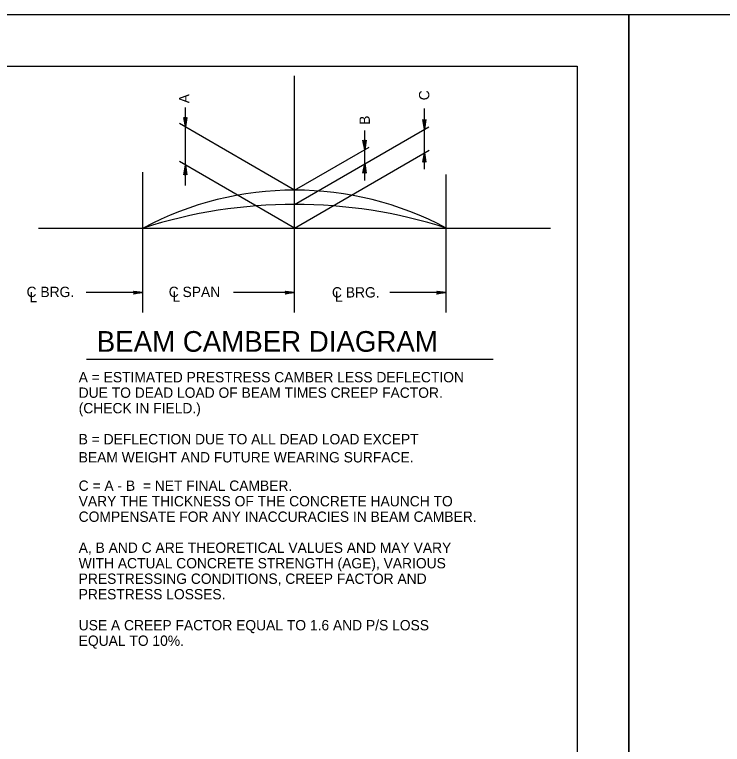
# Model space of a CAD drawing. Extents: x 637933 to 640019, y 298854 to 300042.
# Drawn here: x 638646.7 to 638852.1, y 299830.3 to 300042.1 of the extents above; entities that cross this region are included whole.
import ezdxf

# ---------------------------------------------------------------- set-up
doc = ezdxf.new("R2010")
doc.units = 0
doc.layers.add('1', color=7, linetype='Continuous')
doc.layers.add('PLT-BNDY', color=7, linetype='Continuous')

msp = doc.modelspace()

# ---------------------------------------------------------------- linework, layer by layer
at = {"layer": '1'}
for p, q in [((638023.93, 300027.12), (638809.94, 300027.12)), ((638809.94, 300027.12), (638809.94, 299463.12)), ((638727.89, 299955.63), (638727.89, 300024.38)), ((638696.26, 300009.5), (638696.26, 300015.13)), ((638765.64, 300008.88), (638765.64, 300014.88)), ((638727.89, 299991.13), (638694.51, 300010.5)), ((638696.26, 299998.5), (638696.26, 300009.5)), ((638727.89, 299987), (638766.89, 300009.5)), ((638748.26, 300002.88), (638748.26, 300008.5)), ((638765.64, 300002), (638765.64, 300008.75)), ((638727.89, 299991.13), (638749.51, 300003.63)), ((638727.89, 299980.13), (638767.01, 300002.75)), ((638748.26, 299998.88), (638748.26, 300002.88)), ((638765.64, 299997.25), (638765.64, 300002)), ((638727.89, 299980.13), (638694.51, 299999.5)), ((638696.26, 299992.5), (638696.26, 299998.38)), ((638748.26, 299994), (638748.26, 299998.88)), ((638683.89, 299955.63), (638683.89, 299996.38)), ((638771.89, 299955.63), (638771.89, 299995.75)), ((638727.89, 299991.13), (638727.89, 299991.13)), ((638727.89, 299987), (638727.89, 299987)), ((638653.64, 299980.13), (638802.14, 299980.13)), ((638683.89, 299980.13), (638683.89, 299980.13)), ((638727.89, 299980.13), (638727.89, 299980.13)), ((638771.89, 299980.13), (638771.89, 299980.13)), ((638683.89, 299961.5), (638667.39, 299961.5)), ((638727.89, 299961.5), (638710.14, 299961.5)), ((638771.89, 299961.5), (638755.51, 299961.5)), ((638785.51, 299942), (638667.51, 299942))]:
    msp.add_line(p, q, dxfattribs=at)
for points in [[(638696.51, 300012.13), (638696.39, 300012.13), (638696.26, 300009.5), (638696.51, 300012.13), (638696.64, 300012.25), (638696.26, 300009.5), (638696.14, 300012.13), (638695.89, 300012.13), (638696.26, 300009.5), (638695.76, 300012.25), (638695.89, 300012.13)], [(638766.01, 300011.5), (638765.76, 300011.38), (638765.64, 300008.88), (638766.01, 300011.5), (638766.01, 300011.63), (638765.64, 300008.88), (638765.51, 300011.38), (638765.26, 300011.5), (638765.64, 300008.88), (638765.14, 300011.63), (638765.26, 300011.5)], [(638748.51, 300005.5), (638748.39, 300005.38), (638748.26, 300002.88), (638748.51, 300005.5), (638748.64, 300005.63), (638748.26, 300002.88), (638748.14, 300005.38), (638747.89, 300005.5), (638748.26, 300002.88), (638747.76, 300005.63), (638747.89, 300005.5)], [(638765.26, 299999.38), (638765.51, 299999.5), (638765.64, 300002), (638765.26, 299999.38), (638765.14, 299999.25), (638765.64, 300002), (638765.76, 299999.5), (638765.89, 299999.38), (638765.64, 300002), (638766.01, 299999.25), (638765.89, 299999.38)], [(638695.89, 299995.75), (638696.14, 299995.88), (638696.26, 299998.38), (638695.89, 299995.75), (638695.76, 299995.63), (638696.26, 299998.38), (638696.39, 299995.88), (638696.51, 299995.75), (638696.26, 299998.38), (638696.64, 299995.63), (638696.51, 299995.75)], [(638747.89, 299996.25), (638748.14, 299996.38), (638748.26, 299998.88), (638747.89, 299996.25), (638747.76, 299996.13), (638748.26, 299998.88), (638748.39, 299996.38), (638748.51, 299996.25), (638748.26, 299998.88), (638748.64, 299996.13), (638748.51, 299996.25)], [(638681.26, 299961.75), (638681.39, 299961.63), (638683.89, 299961.5), (638681.26, 299961.75), (638681.14, 299961.88), (638683.89, 299961.5), (638681.39, 299961.38), (638681.39, 299961.13), (638683.89, 299961.5), (638681.14, 299961), (638681.39, 299961.13)], [(638725.26, 299961.75), (638725.39, 299961.63), (638727.89, 299961.5), (638725.26, 299961.75), (638725.14, 299961.88), (638727.89, 299961.5), (638725.39, 299961.38), (638725.39, 299961.13), (638727.89, 299961.5), (638725.14, 299961), (638725.39, 299961.13)], [(638769.26, 299961.75), (638769.39, 299961.63), (638771.89, 299961.5), (638769.26, 299961.75), (638769.14, 299961.88), (638771.89, 299961.5), (638769.39, 299961.38), (638769.26, 299961.13), (638771.89, 299961.5), (638769.14, 299961), (638769.26, 299961.13)]]:
    msp.add_lwpolyline(points, dxfattribs=at)
for centre, radius, start, end in [((638727.94, 299897.66), 93.5, 61.9275, 118.0725), ((638727.94, 299842.8), 144.23, 72.2387, 107.7613)]:
    msp.add_arc(centre, radius, start, end, dxfattribs=at)
at = {"layer": 'PLT-BNDY'}
for points in [[(637983.93, 300042.12), (638824.93, 300042.12), (638824.93, 299448.12), (637983.93, 299448.12)], [(638824.93, 300042.12), (639665.93, 300042.12), (639665.93, 299448.12), (638824.93, 299448.12)]]:
    msp.add_lwpolyline(points, close=True, dxfattribs=at)

# ---------------------------------------------------------------- texts
at = {"layer": '1'}
for s, p in [('A', (638697.39, 300016.38)), ('C', (638767.01, 300017.25)), ('B', (638749.76, 300010.13))]:
    msp.add_text(s, height=3, rotation=90, dxfattribs=at).set_placement(p)
for s, height, p in [('C BRG.', 3, (638650.14, 299960.13)), ('L', 3, (638651.01, 299958.63)), ('C SPAN', 3, (638691.39, 299960.13)), ('L', 3, (638692.51, 299958.75)), ('C BRG.', 3, (638738.76, 299960)), ('L', 3, (638739.64, 299958.75)), ('BEAM CAMBER DIAGRAM', 6, (638670.51, 299944.25)), ('A = ESTIMATED PRESTRESS CAMBER LESS DEFLECTION', 3, (638665.26, 299935.38)), ('DUE TO DEAD LOAD OF BEAM TIMES CREEP FACTOR.', 3, (638665.26, 299930.88)), ('(CHECK IN FIELD.)', 3, (638665.26, 299926.38)), ('B = DEFLECTION DUE TO ALL DEAD LOAD EXCEPT ', 3, (638665.26, 299917.38)), ('BEAM WEIGHT AND FUTURE WEARING SURFACE.', 3, (638665.26, 299912.13)), ('C = A - B  = NET FINAL CAMBER. ', 3, (638665.26, 299903.88)), ('VARY THE THICKNESS OF THE CONCRETE HAUNCH TO', 3, (638665.26, 299899.38)), ('COMPENSATE FOR ANY INACCURACIES IN BEAM CAMBER.', 3, (638665.26, 299894.88)), ('A, B AND C ARE THEORETICAL VALUES AND MAY VARY', 3, (638665.26, 299885.88)), ('WITH ACTUAL CONCRETE STRENGTH (AGE), VARIOUS', 3, (638665.26, 299881.38)), ('PRESTRESSING CONDITIONS, CREEP FACTOR AND', 3, (638665.26, 299876.88)), ('PRESTRESS LOSSES.', 3, (638665.26, 299872.38)), ('USE A CREEP FACTOR EQUAL TO 1.6 AND P/S LOSS', 3, (638665.26, 299863.38)), ('EQUAL TO 10%.', 3, (638665.26, 299858.88))]:
    msp.add_text(s, height=height, dxfattribs=at).set_placement(p)

doc.saveas('drawing.dxf')
